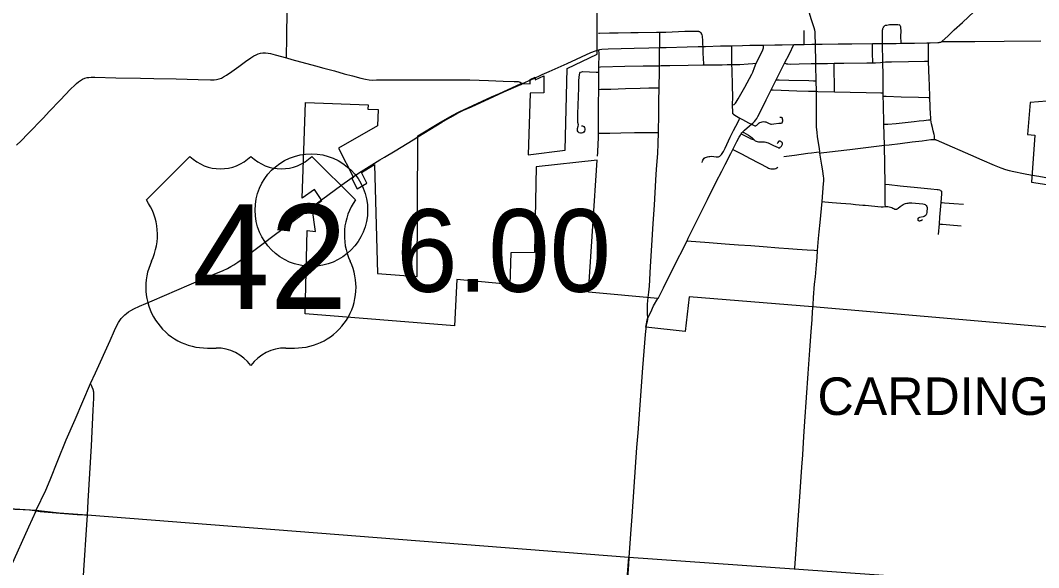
# Model space of a CAD drawing. Extents: x 1815539 to 1947826, y 273303 to 993194.
# Drawn here: x 1848246 to 1861816, y 904048 to 911339 of the extents above; entities that cross this region are included whole.
import ezdxf

# ---------------------------------------------------------------- set-up
doc = ezdxf.new("R2010")
doc.units = 0
for name, color, linetype in [('Default', 7, 'Continuous'), ('GM_X_City_Street', 7, 'Continuous'), ('GM_X_Corporation', 7, 'Continuous'), ('GM_X_Corporation_Text', 7, 'Continuous'), ('GM_X_County_Road', 7, 'Continuous'), ('GM_X_State_Route', 7, 'Continuous'), ('GM_X_Township', 7, 'Continuous'), ('GM_X_Township_Road', 7, 'Continuous'), ('GM_X_US_Route', 7, 'Continuous'), ('PV_X_Shoulder', 7, 'Continuous')]:
    doc.layers.add(name, color=color, linetype=linetype)

msp = doc.modelspace()

# ---------------------------------------------------------------- linework, layer by layer
at = {"layer": 'Default'}
msp.add_circle((1852124, 908811), 750, dxfattribs=at)
at = {"layer": 'GM_X_City_Street'}
for points in [[(1859736, 911031), (1859736, 911048), (1859736, 911079), (1859736, 911143), (1859736, 911191), (1859737, 911207), (1859739, 911222), (1859741, 911231), (1859744, 911238), (1859747, 911246), (1859750, 911252), (1859755, 911259), (1859760, 911265)], [(1859760, 911265), (1859768, 911270), (1859777, 911274), (1859785, 911276), (1859793, 911277), (1859826, 911282), (1859859, 911284), (1859892, 911285), (1859924, 911284), (1859941, 911282), (1859957, 911278)], [(1859982, 911034), (1859982, 911051), (1859981, 911119), (1859982, 911203), (1859980, 911237), (1859979, 911253), (1859976, 911261), (1859972, 911268), (1859964, 911274), (1859957, 911278)], [(1855951, 911168), (1855962, 911168), (1856096, 911171), (1856214, 911173), (1856379, 911176), (1856480, 911178), (1856721, 911180), (1856767, 911180)], [(1856767, 911180), (1856787, 911180), (1856849, 911180), (1856934, 911186), (1857017, 911190), (1857100, 911195), (1857165, 911196), (1857247, 911196), (1857264, 911196), (1857281, 911194), (1857288, 911193), (1857295, 911190), (1857301, 911187), (1857306, 911183), (1857312, 911178), (1857319, 911170)], [(1856769, 910977), (1856769, 911005), (1856768, 911068), (1856767, 911147), (1856767, 911180)], [(1857343, 910991), (1857342, 911016), (1857340, 911081), (1857338, 911114), (1857335, 911130), (1857330, 911145), (1857325, 911157), (1857319, 911170)], [(1858693, 911019), (1858693, 911040), (1858693, 911068), (1858692, 911205)], [(1855956, 910717), (1855957, 910893), (1855954, 910948)], [(1856763, 910735), (1856763, 910799), (1856762, 910867), (1856762, 910942), (1856763, 910959), (1856769, 910977)], [(1857352, 910747), (1857352, 910760), (1857347, 910901), (1857345, 910959), (1857343, 910991)], [(1857729, 910751), (1857726, 910926), (1857725, 910976), (1857725, 911002)], [(1858053, 910768), (1858054, 910772), (1858081, 910831), (1858134, 910933), (1858145, 910958), (1858150, 910973), (1858151, 910983), (1858151, 910999), (1858151, 911011)], [(1858431, 910769), (1858495, 910895), (1858554, 911017)], [(1859605, 910774), (1859605, 910799), (1859603, 910879), (1859602, 911012), (1859602, 911029)], [(1859739, 910781), (1859736, 911031)], [(1860350, 910796), (1860350, 910810), (1860349, 910908), (1860348, 911017), (1860348, 911040)], [(1860525, 911057), (1860606, 911056), (1860751, 911056), (1860965, 911057), (1861358, 911061), (1861846, 911065)], [(1855956, 910717), (1855979, 910718), (1856303, 910727), (1856546, 910734), (1856694, 910735), (1856763, 910735)], [(1855956, 910648), (1855956, 910697), (1855956, 910717)], [(1856759, 910441), (1856761, 910668), (1856763, 910735)], [(1856763, 910735), (1856787, 910736), (1856900, 910737), (1857145, 910743), (1857342, 910747), (1857352, 910747)], [(1857352, 910747), (1857597, 910749), (1857665, 910751), (1857729, 910751)], [(1857729, 910751), (1857766, 910751), (1857832, 910753), (1857944, 910761), (1858009, 910765), (1858053, 910768)], [(1857738, 910212), (1857739, 910322), (1857735, 910469), (1857730, 910681), (1857729, 910751)], [(1857738, 910212), (1857756, 910220), (1857767, 910228), (1857775, 910238), (1857784, 910251), (1857811, 910292), (1857899, 910449), (1857963, 910563), (1857993, 910621), (1858006, 910650), (1858030, 910711), (1858053, 910768)], [(1858319, 910546), (1858431, 910769)], [(1858431, 910769), (1858445, 910764), (1858456, 910761), (1858474, 910758), (1858511, 910757), (1858624, 910759), (1858786, 910763), (1858842, 910764)], [(1858842, 910764), (1858870, 910765), (1859002, 910765), (1859090, 910767)], [(1859090, 910767), (1859219, 910769), (1859527, 910772), (1859605, 910774)], [(1859095, 910387), (1859095, 910412), (1859095, 910493), (1859092, 910655), (1859091, 910748), (1859090, 910767)], [(1859605, 910774), (1859642, 910774), (1859706, 910777), (1859739, 910781)], [(1859739, 910781), (1859774, 910785), (1859853, 910787), (1860082, 910791), (1860294, 910795), (1860327, 910796), (1860350, 910796)], [(1859744, 910373), (1859743, 910406), (1859742, 910610), (1859739, 910781)], [(1860365, 910312), (1860360, 910479), (1860356, 910561), (1860350, 910794), (1860350, 910796)], [(1855723, 909935), (1855739, 909932), (1855754, 909924), (1855764, 909912), (1855770, 909896), (1855770, 909880), (1855764, 909865), (1855754, 909852), (1855741, 909843), (1855725, 909837), (1855709, 909837), (1855693, 909843), (1855681, 909853), (1855672, 909867), (1855670, 909883), (1855671, 909900), (1855681, 909931), (1855682, 909947), (1855674, 909979), (1855674, 909995), (1855675, 910094), (1855679, 910209), (1855686, 910439), (1855690, 910537), (1855696, 910619), (1855700, 910635), (1855711, 910647), (1855726, 910654), (1855742, 910656), (1855918, 910649), (1855944, 910648), (1855956, 910648)], [(1855954, 910420), (1855954, 910452), (1855956, 910648)], [(1858252, 910413), (1858273, 910456), (1858319, 910546)], [(1858319, 910546), (1858359, 910545), (1858487, 910543), (1858751, 910537), (1858817, 910534), (1858846, 910534)], [(1855949, 909835), (1855950, 909978), (1855952, 910223), (1855954, 910420)], [(1855954, 910420), (1855982, 910421), (1856113, 910424), (1856310, 910431), (1856507, 910436), (1856622, 910439), (1856736, 910442), (1856759, 910441)], [(1856750, 909845), (1856755, 910092), (1856756, 910257), (1856759, 910441)], [(1857991, 909956), (1858008, 909970), (1858031, 909993), (1858047, 910012), (1858060, 910032), (1858075, 910060), (1858112, 910133), (1858185, 910280), (1858252, 910413)], [(1858252, 910413), (1858277, 910412), (1858594, 910402), (1858749, 910397), (1858849, 910394)], [(1858849, 910394), (1858875, 910393), (1859095, 910387)], [(1859095, 910387), (1859303, 910381), (1859516, 910377), (1859714, 910374), (1859744, 910373)], [(1859745, 910331), (1859744, 910373)], [(1859751, 909956), (1859747, 910222), (1859745, 910331)], [(1859745, 910331), (1859783, 910330), (1859985, 910322), (1860215, 910316), (1860342, 910312), (1860365, 910312)], [(1860381, 910016), (1860378, 910059), (1860376, 910075), (1860365, 910312)], [(1857747, 910088), (1857742, 910093), (1857740, 910098), (1857739, 910105), (1857739, 910113), (1857738, 910212)], [(1857331, 909447), (1857334, 909463), (1857339, 909478), (1857348, 909492), (1857359, 909503), (1857373, 909511), (1857389, 909517), (1857404, 909522), (1857420, 909525), (1857436, 909527), (1857453, 909528), (1857485, 909526), (1857518, 909522), (1857534, 909522), (1857550, 909523), (1857565, 909528), (1857578, 909538), (1857589, 909551), (1857598, 909564), (1857615, 909592), (1857637, 909636), (1857707, 909783), (1857751, 909870), (1857810, 909986), (1857826, 910018), (1857835, 910037)], [(1857747, 910088), (1857765, 910076), (1857810, 910050), (1857835, 910037)], [(1857835, 910037), (1857867, 910020), (1857949, 909976), (1857991, 909956)], [(1857991, 909956), (1858026, 909938), (1858032, 909935), (1858038, 909934), (1858046, 909935), (1858053, 909938), (1858061, 909944), (1858066, 909948), (1858076, 909960), (1858081, 909966), (1858087, 909972), (1858094, 909976), (1858101, 909980), (1858117, 909985), (1858133, 909988), (1858149, 909990), (1858165, 909989), (1858181, 909986), (1858196, 909980), (1858224, 909965), (1858240, 909959), (1858247, 909958), (1858256, 909958), (1858288, 909961), (1858352, 909969), (1858385, 909971), (1858392, 909974), (1858397, 909976), (1858398, 909978), (1858400, 909980), (1858402, 909984), (1858404, 909990), (1858405, 909993), (1858405, 909996), (1858405, 910009), (1858403, 910025), (1858401, 910033), (1858400, 910036), (1858397, 910040), (1858394, 910041), (1858390, 910043), (1858382, 910044), (1858368, 910044)], [(1859751, 909956), (1859784, 909958), (1859804, 909958), (1859917, 909967), (1860158, 909993), (1860222, 909999), (1860286, 910005), (1860350, 910012), (1860381, 910016)], [(1860429, 909752), (1860429, 909777), (1860428, 909788), (1860426, 909803), (1860422, 909819), (1860410, 909866), (1860400, 909914), (1860389, 909963), (1860381, 910016)], [(1857852, 909827), (1857861, 909839), (1857871, 909852), (1857874, 909855)], [(1857874, 909855), (1857894, 909877), (1857932, 909909), (1857991, 909956)], [(1857874, 909855), (1857889, 909846), (1857948, 909812), (1857976, 909794), (1857982, 909789), (1857994, 909778), (1858023, 909747)], [(1859760, 909675), (1859751, 909956)], [(1855946, 909700), (1855948, 909766), (1855949, 909835)], [(1855949, 909835), (1855971, 909835), (1856021, 909836), (1856103, 909836), (1856249, 909840), (1856428, 909844), (1856541, 909845), (1856655, 909845), (1856721, 909845), (1856750, 909845)], [(1856613, 907648), (1856621, 907717), (1856628, 907799), (1856644, 908061), (1856661, 908340), (1856670, 908487), (1856679, 908634), (1856695, 908879), (1856714, 909209), (1856725, 909357), (1856739, 909567), (1856745, 909701), (1856750, 909845)], [(1857742, 909621), (1857794, 909726), (1857824, 909784), (1857842, 909812), (1857852, 909827)], [(1857852, 909827), (1857877, 909814), (1857948, 909778), (1857966, 909769), (1857970, 909766), (1857984, 909760), (1858023, 909747)], [(1858023, 909747), (1858038, 909735), (1858051, 909728), (1858065, 909724), (1858082, 909723), (1858114, 909722), (1858147, 909722), (1858163, 909721), (1858179, 909718), (1858195, 909714), (1858210, 909708), (1858284, 909674), (1858343, 909645), (1858351, 909642), (1858358, 909641), (1858366, 909643), (1858373, 909648), (1858378, 909653), (1858384, 909659), (1858388, 909665), (1858393, 909673), (1858400, 909688), (1858401, 909694), (1858401, 909699), (1858401, 909704), (1858399, 909707), (1858397, 909712), (1858392, 909718), (1858386, 909722), (1858379, 909726), (1858371, 909729), (1858363, 909730), (1858355, 909728), (1858348, 909724), (1858338, 909711), (1858332, 909696)], [(1855939, 909530), (1855942, 909580), (1855946, 909700)], [(1857130, 908404), (1857147, 908438), (1857211, 908570), (1857255, 908658), (1857293, 908730), (1857402, 908951), (1857518, 909186), (1857593, 909332), (1857640, 909418), (1857714, 909564), (1857742, 909621)], [(1857742, 909621), (1857768, 909607), (1857854, 909561), (1857970, 909500), (1858201, 909377), (1858216, 909370), (1858231, 909365), (1858247, 909362), (1858264, 909361), (1858280, 909362), (1858296, 909363), (1858312, 909367), (1858327, 909375), (1858340, 909385)], [(1858421, 909526), (1858560, 909543), (1858740, 909568), (1858788, 909575), (1858856, 909584), (1858896, 909589)], [(1859769, 909159), (1859760, 909675)], [(1858931, 908924), (1858949, 909164), (1858951, 909198), (1858952, 909243), (1858950, 909259), (1858939, 909335), (1858927, 909411), (1858900, 909570)], [(1859769, 909159), (1859825, 909153), (1859972, 909137), (1860201, 909113), (1860381, 909097), (1860462, 909088), (1860478, 909086), (1860494, 909082), (1860502, 909079), (1860509, 909075), (1860514, 909070), (1860519, 909065), (1860523, 909057)], [(1859773, 908861), (1859772, 908884), (1859769, 909159)], [(1860517, 908914), (1860527, 909030), (1860526, 909044), (1860526, 909049), (1860523, 909057)], [(1858869, 908273), (1858874, 908327), (1858884, 908435), (1858892, 908521), (1858903, 908645), (1858931, 908924)], [(1858931, 908924), (1858967, 908921), (1859065, 908913), (1859180, 908904), (1859311, 908894), (1859376, 908888), (1859473, 908879), (1859505, 908876), (1859717, 908857), (1859743, 908857), (1859773, 908861)], [(1859773, 908861), (1859808, 908858), (1859825, 908855), (1859842, 908852), (1859857, 908847), (1859872, 908839), (1859886, 908831), (1859898, 908826), (1859901, 908825), (1859904, 908824), (1859908, 908823), (1859915, 908823), (1859917, 908823), (1859920, 908824), (1859924, 908825), (1859932, 908829), (1859945, 908839), (1859971, 908860), (1859998, 908878), (1860012, 908886), (1860027, 908893), (1860043, 908899), (1860059, 908903), (1860075, 908906), (1860091, 908908), (1860124, 908908), (1860173, 908905), (1860272, 908895), (1860288, 908892), (1860303, 908885), (1860316, 908875), (1860324, 908861), (1860329, 908845), (1860330, 908829), (1860326, 908796), (1860324, 908779), (1860321, 908763), (1860315, 908748), (1860304, 908736), (1860290, 908727), (1860275, 908722), (1860227, 908711), (1860218, 908708), (1860213, 908705), (1860212, 908704), (1860210, 908702), (1860207, 908698), (1860205, 908693), (1860205, 908690), (1860205, 908687), (1860206, 908683), (1860207, 908679), (1860210, 908675), (1860216, 908672), (1860224, 908670), (1860234, 908670), (1860241, 908671), (1860249, 908674), (1860256, 908677), (1860268, 908686)], [(1860493, 908628), (1860500, 908718), (1860517, 908914)], [(1860517, 908914), (1860528, 908913), (1860559, 908910), (1860686, 908900), (1860815, 908889)], [(1860481, 908487), (1860493, 908628)], [(1860493, 908628), (1860507, 908626), (1860535, 908624), (1860631, 908614), (1860782, 908601)], [(1856746, 907636), (1856817, 907778), (1856941, 908027), (1857130, 908404)], [(1857130, 908404), (1857183, 908398), (1857248, 908392), (1857427, 908379), (1857639, 908362), (1857818, 908350), (1857981, 908338), (1858144, 908325), (1858353, 908309), (1858484, 908299), (1858596, 908291), (1858730, 908282), (1858826, 908276), (1858869, 908273)], [(1858810, 907550), (1858816, 907648), (1858830, 907825), (1858840, 907923), (1858854, 908084), (1858862, 908181), (1858869, 908273)], [(1858803, 907455), (1858810, 907550)], [(1856587, 907249), (1856594, 907299), (1856602, 907331), (1856607, 907356)]]:
    msp.add_lwpolyline(points, dxfattribs=at)
at = {"layer": 'GM_X_Corporation'}
for points in [[(1863265, 907135), (1858801, 907524), (1857157, 907658), (1857107, 907193), (1856579, 907250), (1856605, 907366), (1856647, 907453), (1856685, 907534), (1856742, 907635), (1855819, 907719), (1855934, 909477), (1855118, 909390), (1855096, 908246), (1854784, 908242), (1854770, 907822), (1854063, 907885), (1854029, 907271), (1852043, 907428), (1852066, 908538), (1852177, 908528), (1852134, 908843), (1852262, 908941), (1852164, 909086), (1852000, 908971), (1852045, 910245), (1852879, 910216), (1852877, 910158), (1853013, 910154), (1853006, 909935), (1852486, 909635), (1852684, 909247), (1852665, 909234), (1852734, 909095), (1852863, 909170), (1852790, 909313), (1852966, 909419), (1853003, 907969), (1853534, 907926), (1853544, 909800), (1853821, 909968), (1854001, 910073), (1854094, 910121), (1854398, 910262), (1854526, 910322), (1854631, 910364), (1854919, 910496), (1855039, 910495), (1855039, 910551), (1855107, 910582), (1855107, 910549), (1855221, 910602), (1855220, 910374), (1855039, 910368), (1855014, 909548), (1855507, 909608), (1855534, 910697), (1855933, 910888), (1855933, 911621)], [(1862812, 910332), (1861702, 910244), (1861668, 909817), (1861766, 909810), (1861720, 909183), (1862559, 909053)]]:
    msp.add_lwpolyline(points, dxfattribs=at)
at = {"layer": 'GM_X_County_Road'}
for points in [[(1848195, 909678), (1848255, 909735), (1848347, 909828), (1848552, 910041), (1848631, 910124), (1848778, 910278), (1848914, 910421), (1848972, 910478), (1848996, 910500), (1849022, 910521), (1849046, 910539), (1849074, 910555), (1849105, 910568), (1849135, 910576), (1849156, 910578), (1849189, 910581), (1849238, 910582), (1849517, 910575), (1849845, 910568), (1850025, 910564), (1850320, 910559), (1850615, 910553), (1850779, 910548), (1850828, 910549), (1850861, 910552), (1850877, 910555), (1850893, 910559), (1850924, 910571), (1850953, 910585), (1850995, 910611), (1851062, 910658), (1851155, 910725), (1851248, 910793), (1851315, 910840), (1851357, 910866), (1851386, 910881), (1851417, 910894), (1851447, 910902), (1851477, 910907), (1851514, 910905), (1851546, 910902), (1851579, 910897), (1851642, 910881), (1851791, 910839)], [(1851791, 910839), (1851863, 910819), (1852180, 910732), (1852290, 910702), (1852433, 910665), (1852559, 910629), (1852670, 910599), (1852781, 910571), (1852845, 910556), (1852894, 910548), (1852941, 910544), (1852993, 910545), (1853077, 910545), (1853172, 910546), (1853257, 910546), (1853630, 910547), (1853768, 910547), (1853975, 910548), (1854041, 910548), (1854237, 910545), (1854483, 910537), (1854680, 910530), (1854827, 910526), (1854861, 910525), (1854881, 910523), (1854893, 910521), (1854905, 910516), (1854919, 910509), (1854936, 910498)], [(1856607, 907356), (1856608, 907364), (1856609, 907380), (1856608, 907396), (1856604, 907412), (1856602, 907428), (1856604, 907543), (1856605, 907560), (1856613, 907648)], [(1858565, 904030), (1858567, 904045), (1858584, 904290), (1858607, 904618), (1858637, 905060), (1858651, 905257), (1858662, 905388), (1858673, 905551), (1858688, 905797), (1858702, 905994), (1858746, 906633), (1858768, 906944), (1858785, 907189), (1858796, 907353), (1858803, 907455)], [(1856359, 904183), (1856381, 904500), (1856397, 904729), (1856425, 905123), (1856462, 905647), (1856477, 905843), (1856542, 906711), (1856575, 907153), (1856585, 907234), (1856587, 907249)], [(1849140, 904747), (1849151, 904932), (1849192, 905669), (1849218, 906144), (1849227, 906307), (1849227, 906329), (1849226, 906347), (1849225, 906371), (1849223, 906385), (1849221, 906399), (1849219, 906406), (1849214, 906422), (1849202, 906452), (1849197, 906465), (1849193, 906476), (1849182, 906502)], [(1843723, 905149), (1843850, 905140), (1844177, 905115), (1844635, 905078), (1844897, 905058), (1845420, 905017), (1845944, 904974), (1846140, 904960), (1846320, 904946), (1846500, 904933), (1846910, 904905), (1847106, 904892), (1847319, 904877), (1847450, 904869), (1847548, 904862), (1847712, 904849), (1847954, 904835), (1848047, 904830), (1848171, 904827), (1848285, 904823), (1848367, 904817), (1848432, 904810), (1848455, 904806)], [(1848455, 904806), (1848481, 904802), (1848511, 904797), (1848775, 904775), (1849004, 904757), (1849102, 904750), (1849140, 904747)], [(1849028, 903004), (1849051, 903376), (1849073, 903720), (1849093, 904015), (1849132, 904620), (1849140, 904747)], [(1856232, 902508), (1856237, 902567), (1856269, 902977), (1856304, 903435), (1856353, 904090), (1856359, 904183)]]:
    msp.add_lwpolyline(points, dxfattribs=at)
at = {"layer": 'GM_X_State_Route'}
for points in [[(1858751, 911452), (1858784, 911353), (1858819, 911244), (1858827, 911213), (1858832, 911181), (1858835, 911149), (1858838, 911021)], [(1858838, 911021), (1858842, 910770)], [(1858842, 910770), (1858842, 910764), (1858843, 910739), (1858846, 910534), (1858849, 910394), (1858849, 910293), (1858849, 910157), (1858853, 909918), (1858858, 909849), (1858864, 909786), (1858890, 909631)], [(1858890, 909631), (1858896, 909589), (1858900, 909570), (1858919, 909573), (1859104, 909595), (1859300, 909620), (1859760, 909675), (1859822, 909682), (1859969, 909700), (1860132, 909720), (1860263, 909736), (1860377, 909750), (1860382, 909750)], [(1860382, 909750), (1860409, 909752), (1860429, 909752), (1860440, 909750), (1860446, 909748), (1860450, 909746), (1860519, 909716), (1860908, 909547), (1861058, 909483), (1861223, 909412), (1861314, 909376), (1861376, 909354), (1861423, 909340), (1861486, 909324), (1861614, 909298), (1861731, 909278)], [(1861731, 909278), (1861819, 909262), (1862031, 909224), (1862569, 909124)]]:
    msp.add_lwpolyline(points, dxfattribs=at)
at = {"layer": 'GM_X_Township'}
for points in [[(1853740, 885139), (1853912, 887891), (1854256, 893376), (1854601, 899118), (1855968, 899037), (1856227, 902512), (1856354, 904189), (1858556, 904033), (1863007, 903717), (1863265, 907135), (1863306, 907714), (1863375, 908580), (1863406, 908966), (1863544, 910397), (1864246, 910459), (1864806, 910520), (1866935, 910696), (1872022, 911301), (1871903, 909711), (1873264, 909583), (1874571, 909455), (1879532, 909040), (1882082, 908847)], [(1840896, 907530), (1841789, 907648), (1841735, 905294), (1841826, 905293), (1842755, 905225), (1843722, 905154), (1847517, 904873), (1848451, 904813), (1848761, 904780), (1849137, 904752), (1856354, 904189)]]:
    msp.add_lwpolyline(points, dxfattribs=at)
at = {"layer": 'GM_X_Township_Road'}
msp.add_lwpolyline([(1851791, 910839), (1851792, 910859), (1851794, 910908), (1851799, 911056), (1851801, 911531), (1851802, 911679), (1851803, 911868)], dxfattribs=at)
at = {"layer": 'GM_X_US_Route'}
for points in [[(1860369, 911041), (1860474, 911045), (1860488, 911046), (1860499, 911048), (1860507, 911049), (1860513, 911051), (1860519, 911053), (1860525, 911057), (1860608, 911134), (1860692, 911213), (1860800, 911313), (1860958, 911456)], [(1855182, 910608), (1855201, 910616), (1855294, 910658), (1855533, 910765), (1855849, 910909), (1855909, 910934), (1855937, 910944)], [(1855937, 910944), (1855954, 910948), (1855969, 910952), (1855996, 910955), (1856079, 910959), (1856424, 910968), (1856621, 910973), (1856769, 910977), (1856851, 910979), (1857131, 910986), (1857279, 910990), (1857343, 910991), (1857377, 910992), (1857575, 910998), (1857725, 911002), (1857867, 911005)], [(1857867, 911005), (1857969, 911008), (1858151, 911011), (1858298, 911013), (1858397, 911014), (1858554, 911017), (1858666, 911019)], [(1858666, 911019), (1858677, 911019), (1858693, 911019), (1858792, 911020), (1858838, 911021), (1858929, 911023), (1859144, 911026)], [(1859144, 911026), (1859159, 911026), (1859324, 911026), (1859602, 911029), (1859736, 911031), (1859768, 911031), (1859917, 911033), (1859982, 911034), (1860161, 911036), (1860327, 911039), (1860348, 911040), (1860369, 911041)], [(1854936, 910498), (1855018, 910534)], [(1855018, 910534), (1855087, 910565)], [(1855087, 910565), (1855182, 910608)], [(1853544, 909787), (1853864, 909983), (1853977, 910050), (1854063, 910098), (1854151, 910141), (1854256, 910189), (1854555, 910325), (1854689, 910386), (1854914, 910487), (1854936, 910498)], [(1852967, 909435), (1853036, 909479), (1853100, 909517), (1853240, 909603), (1853480, 909749), (1853544, 909787)], [(1852684, 909257), (1852787, 909326)], [(1852787, 909326), (1852967, 909435)], [(1852261, 908948), (1852530, 909146), (1852637, 909223), (1852666, 909244), (1852684, 909257)], [(1852133, 908854), (1852261, 908948)], [(1848455, 904806), (1848458, 904814), (1848585, 905081), (1848644, 905216), (1848745, 905476), (1848858, 905749), (1848974, 906021), (1849182, 906502), (1849247, 906642), (1849441, 907075), (1849502, 907209), (1849537, 907283), (1849553, 907312), (1849571, 907340), (1849591, 907366), (1849613, 907391), (1849636, 907415), (1849661, 907436), (1849688, 907456), (1849716, 907473), (1849760, 907496), (1849834, 907531), (1850000, 907602), (1850497, 907814), (1850828, 907956), (1850948, 908007), (1851007, 908035), (1851050, 908058), (1851092, 908084), (1851146, 908120), (1851266, 908206), (1851463, 908353), (1851647, 908489), (1851844, 908636), (1852054, 908792), (1852133, 908854)], [(1848122, 904066), (1848357, 904590), (1848455, 904806)]]:
    msp.add_lwpolyline(points, dxfattribs=at)
at = {"layer": 'PV_X_Shoulder'}
for p, q in [((1850506, 909527), (1849926, 908947)), ((1852710, 908947), (1852130, 909527)), ((1850738, 906974), (1850854, 906974)), ((1851782, 906974), (1851898, 906974))]:
    msp.add_line(p, q, dxfattribs=at)
for centre, radius, start, end in [((1850912, 909941), 580, 225.573, 314.427), ((1851724, 909941), 580, 225.573, 314.427), ((1849260, 908481), 812, 334.5471, 35.0009), ((1853375, 908481), 812, 144.9991, 205.4529), ((1850729, 907786), 812, 154.8319, 270.6383), ((1851907, 907786), 812, 269.3617, 25.1681), ((1850854, 906394), 580, 36.8699, 90), ((1851782, 906394), 580, 90, 143.1301)]:
    msp.add_arc(centre, radius, start, end, dxfattribs=at)

# ---------------------------------------------------------------- texts
at = {"layer": 'Default'}
msp.add_text('6.00', height=1100, dxfattribs=at).set_placement((1853254, 907723))
at = {"layer": 'GM_X_Corporation_Text'}
msp.add_text('CARDINGTON', height=500, rotation=0, dxfattribs=at).set_placement((1858869, 906082))
at = {"layer": 'PV_X_Shoulder'}
msp.add_text('42', height=1392.2, dxfattribs=at).set_placement((1850534, 907496))

doc.saveas('drawing.dxf')
